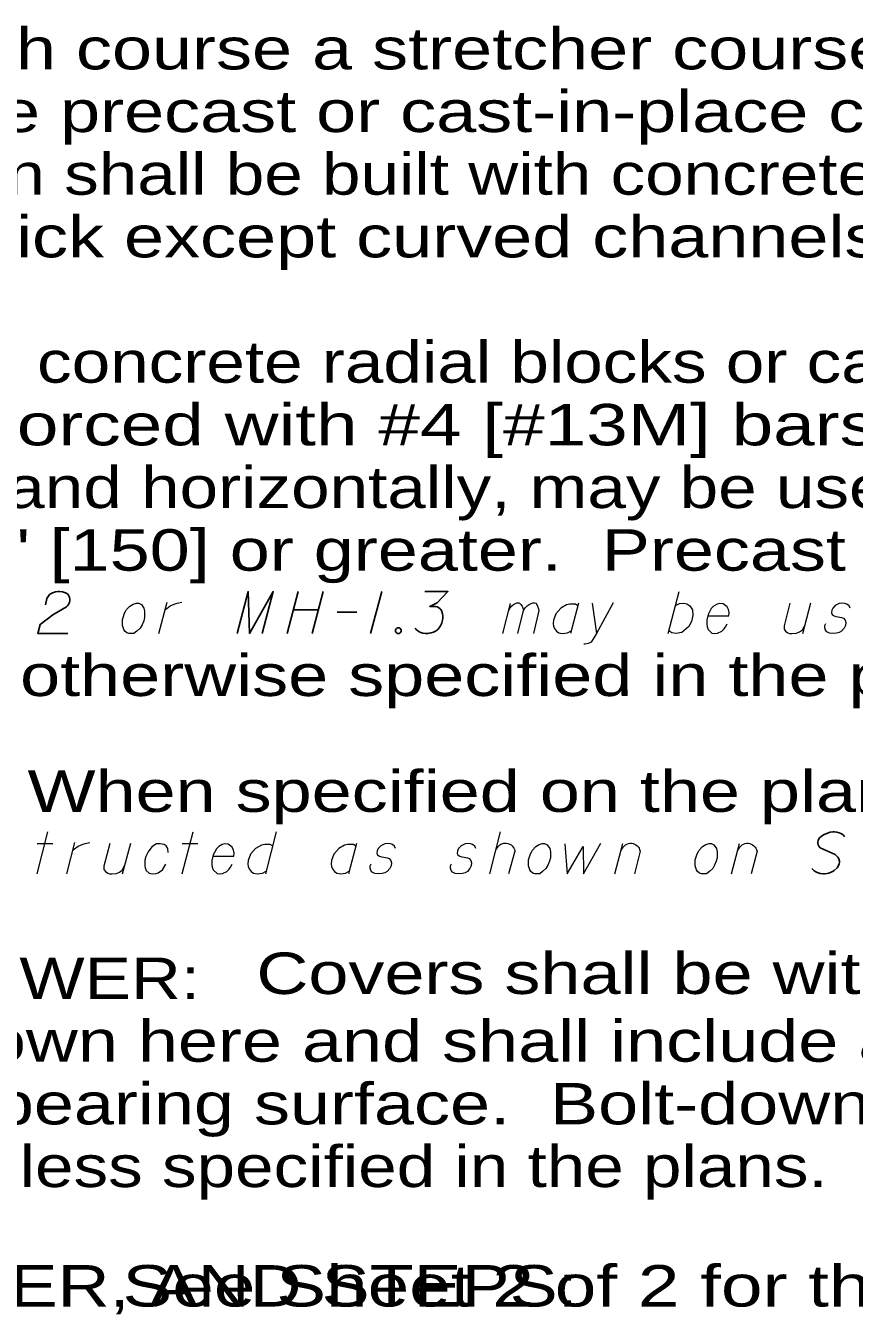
# Model space of a CAD drawing. Extents: x 1083.1 to 1117.1, y 697.4 to 741.4.
# Drawn here: x 1106.726 to 1109.847, y 730.897 to 735.749 of the extents above; entities that cross this region are included whole.
import ezdxf

# ---------------------------------------------------------------- set-up
doc = ezdxf.new("R2010")
doc.units = 0
doc.header["$LTSCALE"] = 0.062
doc.layers.add('1', color=7, linetype='Continuous', lineweight=13)

msp = doc.modelspace()

# ---------------------------------------------------------------- linework, layer by layer
at = {"layer": '1', "lineweight": 25}
for p, q in [((1107.7525, 733.61842), (1107.71033, 733.46108)), ((1107.84667, 733.61842), (1107.8045, 733.46108)), ((1108.06717, 733.61842), (1108.025, 733.46108)), ((1107.73392, 733.54908), (1107.82808, 733.54908)), ((1107.89867, 733.54042), (1107.973, 733.54042))]:
    msp.add_line(p, q, dxfattribs=at)
at = {"layer": '1'}
for p, q in [((1109.14617, 733.46108), (1109.18708, 733.61842)), ((1107.22725, 733.46108), (1107.25817, 733.57883)), ((1108.52308, 733.46108), (1108.55158, 733.57383)), ((1108.58, 733.46108), (1108.60108, 733.54658)), ((1108.808, 733.57508), (1108.77825, 733.46108)), ((1108.86, 733.57508), (1108.87608, 733.46108)), ((1109.65292, 733.46108), (1109.68383, 733.57633)), ((1106.769, 732.55567), (1106.80983, 732.713)), ((1107.31533, 732.55567), (1107.35617, 732.713)), ((1107.66958, 732.713), (1107.62875, 732.55567)), ((1108.47358, 732.55567), (1108.5145, 732.713)), ((1106.769, 732.66967), (1106.82842, 732.66967)), ((1106.8805, 732.55567), (1106.91142, 732.67342)), ((1107.09108, 732.55567), (1107.122, 732.67092)), ((1107.31533, 732.66967), (1107.37475, 732.66967)), ((1107.97192, 732.66967), (1107.94217, 732.55567)), ((1108.94442, 732.55567), (1108.97533, 732.66967)), ((1109.38417, 732.55567), (1109.41517, 732.66967))]:
    msp.add_line(p, q, dxfattribs=at)
at = {"layer": '1', "lineweight": 25}
for points in [[(1106.79983, 733.56892), (1106.806, 733.59242), (1106.81592, 733.60733), (1106.82708, 733.6135), (1106.83825, 733.61725), (1106.84692, 733.61842), (1106.85308, 733.61842), (1106.86425, 733.61725), (1106.87167, 733.61475), (1106.87542, 733.6135), (1106.88283, 733.60975), (1106.8865, 733.60483), (1106.889, 733.59983), (1106.89025, 733.59617), (1106.8915, 733.59117), (1106.8915, 733.585), (1106.89025, 733.57883), (1106.889, 733.57508), (1106.8865, 733.57017), (1106.88283, 733.56517), (1106.87908, 733.5615), (1106.82833, 733.5305), (1106.78, 733.49458), (1106.77133, 733.46108), (1106.88408, 733.46108)], [(1107.52208, 733.46108), (1107.56417, 733.61842), (1107.56917, 733.46108), (1107.65833, 733.61842), (1107.61617, 733.46108)], [(1108.22942, 733.61842), (1108.31617, 733.61842), (1108.27525, 733.57633), (1108.248, 733.56267), (1108.27033, 733.56267), (1108.27525, 733.5615), (1108.27775, 733.56025), (1108.28025, 733.559), (1108.28267, 733.55775), (1108.28767, 733.554), (1108.29017, 733.55033), (1108.29258, 733.54658), (1108.29383, 733.54292), (1108.29633, 733.53425), (1108.29758, 733.52675), (1108.29758, 733.52308), (1108.29758, 733.51808), (1108.29633, 733.51067), (1108.29508, 733.50575), (1108.29383, 733.50075), (1108.29258, 733.49708), (1108.29142, 733.49458), (1108.29017, 733.49208), (1108.28892, 733.48958), (1108.28642, 733.48592), (1108.28267, 733.48092), (1108.279, 733.47725), (1108.2765, 733.47475), (1108.27275, 733.47225), (1108.26908, 733.46983), (1108.26408, 733.46733), (1108.26167, 733.46608), (1108.253, 733.46358), (1108.2455, 733.46233), (1108.24058, 733.46108), (1108.23192, 733.46108), (1108.222, 733.46233), (1108.21825, 733.46358), (1108.21458, 733.46483), (1108.21083, 733.46608), (1108.20717, 733.46858), (1108.20342, 733.471), (1108.19725, 733.476), (1108.1935, 733.48092)], [(1109.81033, 732.6945), (1109.80783, 732.69942), (1109.80167, 732.70433), (1109.79667, 732.70683), (1109.7905, 732.70933), (1109.78183, 732.71183), (1109.77192, 732.713), (1109.76575, 732.713), (1109.75583, 732.71183), (1109.73967, 732.70558), (1109.731, 732.70192), (1109.72233, 732.69567), (1109.71617, 732.69075), (1109.71367, 732.687), (1109.71125, 732.68083), (1109.71, 732.67583), (1109.71, 732.67092), (1109.71125, 732.66475), (1109.71367, 732.65975), (1109.71742, 732.65483), (1109.71867, 732.65358), (1109.77442, 732.62758), (1109.78558, 732.61767), (1109.788, 732.61392), (1109.78925, 732.61142), (1109.79175, 732.60275), (1109.79175, 732.59783), (1109.7905, 732.59283), (1109.788, 732.58667), (1109.78308, 732.578), (1109.77067, 732.56808), (1109.767, 732.56558), (1109.75708, 732.56067), (1109.75083, 732.55817), (1109.74467, 732.55692), (1109.73475, 732.55567), (1109.731, 732.55567), (1109.71867, 732.55692), (1109.71125, 732.55942), (1109.705, 732.56192), (1109.69633, 732.56683), (1109.68767, 732.5755)]]:
    msp.add_lwpolyline(points, dxfattribs=at)
at = {"layer": '1'}
for points in [[(1107.143, 733.57508), (1107.15167, 733.57508), (1107.16158, 733.57017), (1107.17142, 733.5565), (1107.17267, 733.55033), (1107.17392, 733.54408), (1107.17392, 733.53917), (1107.17392, 733.52058), (1107.17025, 733.50817), (1107.164, 733.49333), (1107.15658, 733.48092), (1107.14417, 733.46983), (1107.13308, 733.46108), (1107.1145, 733.46108), (1107.107, 733.46358), (1107.09958, 733.46983), (1107.09592, 733.476), (1107.09092, 733.49083), (1107.09092, 733.51317), (1107.09342, 733.52058), (1107.09833, 733.53667), (1107.10333, 733.54533), (1107.10583, 733.55033), (1107.11817, 733.56392), (1107.13058, 733.57142)], [(1108.67183, 732.66967), (1108.6805, 732.66967), (1108.69042, 732.66475), (1108.70033, 732.65108), (1108.70158, 732.64492), (1108.70283, 732.63867), (1108.70283, 732.63375), (1108.70283, 732.61517), (1108.69908, 732.60275), (1108.69292, 732.58792), (1108.68542, 732.5755), (1108.67308, 732.56442), (1108.66192, 732.55567), (1108.64333, 732.55567), (1108.63592, 732.55817), (1108.6285, 732.56442), (1108.62475, 732.57058), (1108.61983, 732.58542), (1108.61983, 732.60775), (1108.62225, 732.61517), (1108.62725, 732.63125), (1108.63217, 732.63992), (1108.63467, 732.64492), (1108.64708, 732.6585), (1108.65942, 732.666)], [(1109.29992, 732.66967), (1109.30858, 732.66967), (1109.3185, 732.66475), (1109.32842, 732.65108), (1109.32967, 732.64492), (1109.33092, 732.63867), (1109.33092, 732.63375), (1109.33092, 732.61517), (1109.32717, 732.60275), (1109.321, 732.58792), (1109.31358, 732.5755), (1109.30117, 732.56442), (1109.29, 732.55567), (1109.27142, 732.55567), (1109.264, 732.55817), (1109.25658, 732.56442), (1109.25283, 732.57058), (1109.24792, 732.58542), (1109.24792, 732.60775), (1109.25033, 732.61517), (1109.25533, 732.63125), (1109.26025, 732.63992), (1109.26275, 732.64492), (1109.27517, 732.6585), (1109.2875, 732.666)]]:
    msp.add_lwpolyline(points, close=True, dxfattribs=at)
for points in [[(1107.25075, 733.55033), (1107.25692, 733.55525), (1107.27058, 733.56517), (1107.28542, 733.57142), (1107.29658, 733.57508), (1107.31392, 733.57883)], [(1108.54408, 733.54408), (1108.55033, 733.55775), (1108.5565, 733.56517), (1108.56392, 733.57017), (1108.57133, 733.57383), (1108.57633, 733.57633), (1108.58375, 733.57633), (1108.58625, 733.57508), (1108.59117, 733.57017), (1108.59617, 733.56392), (1108.59983, 733.55283), (1108.60108, 733.54658), (1108.60725, 733.55775), (1108.61475, 733.56517), (1108.62217, 733.57017), (1108.62958, 733.57383), (1108.63575, 733.57633), (1108.642, 733.57633), (1108.64692, 733.57508), (1108.65067, 733.57017), (1108.65433, 733.56392), (1108.65808, 733.55283), (1108.65933, 733.54658), (1108.63825, 733.46108)], [(1108.8055, 733.56517), (1108.79683, 733.57142), (1108.77575, 733.57142), (1108.76342, 733.56892), (1108.74108, 733.5565), (1108.7225, 733.53425), (1108.71383, 733.51067), (1108.71258, 733.49825), (1108.71383, 733.48842), (1108.71758, 733.47967), (1108.725, 733.46983), (1108.73367, 733.46358), (1108.74725, 733.46108), (1108.75717, 733.46233), (1108.76708, 733.46358), (1108.78075, 733.471)], [(1108.93933, 733.57633), (1108.87608, 733.46108), (1108.85633, 733.42767), (1108.85133, 733.42517), (1108.84517, 733.42275), (1108.83275, 733.42025), (1108.82783, 733.42025)], [(1109.17342, 733.56642), (1109.18833, 733.57383), (1109.20442, 733.57508), (1109.21683, 733.57258), (1109.22792, 733.56517), (1109.23783, 733.54908), (1109.23908, 733.528), (1109.23417, 733.50575), (1109.22425, 733.48717), (1109.197, 733.46483), (1109.17592, 733.46108), (1109.15983, 733.46358), (1109.14867, 733.471)], [(1109.29483, 733.52675), (1109.37408, 733.52675), (1109.37533, 733.53917), (1109.37292, 733.55033), (1109.36792, 733.5615), (1109.35308, 733.57258), (1109.34067, 733.57383), (1109.33075, 733.57142), (1109.31717, 733.56392), (1109.3085, 733.55525), (1109.301, 733.54167), (1109.29608, 733.53175), (1109.29108, 733.51067), (1109.29108, 733.49708), (1109.29233, 733.48592), (1109.29608, 733.476), (1109.31092, 733.46233), (1109.32083, 733.46108), (1109.33075, 733.46233), (1109.332, 733.46233), (1109.34808, 733.46983), (1109.35675, 733.4785), (1109.3605, 733.48467), (1109.36175, 733.48592), (1109.36792, 733.49708)], [(1109.60458, 733.57508), (1109.58225, 733.48958), (1109.58225, 733.47725), (1109.58842, 733.46983), (1109.59717, 733.46358), (1109.60333, 733.46108), (1109.612, 733.46108), (1109.62933, 733.46233), (1109.6405, 733.46733), (1109.65167, 733.47475), (1109.66158, 733.49333)], [(1109.83125, 733.5565), (1109.82758, 733.56517), (1109.81883, 733.57142), (1109.81142, 733.57383), (1109.80025, 733.57508), (1109.79042, 733.57383), (1109.7755, 733.56642), (1109.76558, 733.5565), (1109.76192, 733.54783), (1109.76067, 733.53792), (1109.76308, 733.53175), (1109.76808, 733.528), (1109.77058, 733.52675), (1109.778, 733.52433), (1109.78667, 733.52308), (1109.79908, 733.52058), (1109.8065, 733.51808), (1109.81267, 733.51067), (1109.81517, 733.502), (1109.81392, 733.49083), (1109.809, 733.48092), (1109.79908, 733.46983), (1109.79042, 733.46483), (1109.7805, 733.46233), (1109.76808, 733.46108), (1109.75325, 733.46233), (1109.74333, 733.46733), (1109.73833, 733.4735), (1109.73583, 733.48217), (1109.73583, 733.49083), (1109.73958, 733.49825)], [(1106.904, 732.64492), (1106.91017, 732.64983), (1106.92383, 732.65975), (1106.93867, 732.666), (1106.94983, 732.66967), (1106.96717, 732.67342)], [(1107.04275, 732.66967), (1107.02042, 732.58417), (1107.02042, 732.57183), (1107.02667, 732.56442), (1107.03533, 732.55817), (1107.0415, 732.55567), (1107.05017, 732.55567), (1107.0675, 732.55692), (1107.07867, 732.56192), (1107.08983, 732.56933), (1107.09975, 732.58792)], [(1107.262, 732.63625), (1107.26075, 732.65108), (1107.25458, 732.661), (1107.24717, 732.666), (1107.23225, 732.66842), (1107.21867, 732.66842), (1107.20133, 732.65733), (1107.18767, 732.63867), (1107.17775, 732.62017), (1107.17408, 732.6065), (1107.17408, 732.58542), (1107.17533, 732.578), (1107.18025, 732.56808), (1107.19142, 732.55817), (1107.20383, 732.55567), (1107.21742, 732.55692), (1107.22483, 732.55942), (1107.241, 732.57058), (1107.25333, 732.59167)], [(1107.4305, 732.62133), (1107.50975, 732.62133), (1107.511, 732.63375), (1107.50858, 732.64492), (1107.50358, 732.65608), (1107.48875, 732.66717), (1107.47633, 732.66842), (1107.46642, 732.666), (1107.45283, 732.6585), (1107.44417, 732.64983), (1107.43667, 732.63625), (1107.43175, 732.62633), (1107.42675, 732.60525), (1107.42675, 732.59167), (1107.428, 732.5805), (1107.43175, 732.57058), (1107.44658, 732.55692), (1107.4565, 732.55567), (1107.46642, 732.55692), (1107.46767, 732.55692), (1107.48375, 732.56442), (1107.49242, 732.57308), (1107.49617, 732.57925), (1107.49742, 732.5805), (1107.50358, 732.59167)], [(1107.656, 732.661), (1107.64733, 732.666), (1107.62625, 732.666), (1107.61383, 732.6635), (1107.59158, 732.65108), (1107.573, 732.62883), (1107.56433, 732.60525), (1107.56308, 732.59283), (1107.56433, 732.583), (1107.568, 732.57425), (1107.57542, 732.56442), (1107.58417, 732.55817), (1107.59775, 732.55567), (1107.60767, 732.55692), (1107.61758, 732.55817), (1107.63117, 732.56558)], [(1107.96942, 732.65975), (1107.96075, 732.666), (1107.93967, 732.666), (1107.92725, 732.6635), (1107.905, 732.65108), (1107.88642, 732.62883), (1107.87775, 732.60525), (1107.8765, 732.59283), (1107.87775, 732.583), (1107.88142, 732.57425), (1107.88892, 732.56442), (1107.89758, 732.55817), (1107.91117, 732.55567), (1107.92108, 732.55692), (1107.931, 732.55817), (1107.94467, 732.56558)], [(1108.11933, 732.65108), (1108.11558, 732.65975), (1108.10692, 732.666), (1108.0995, 732.66842), (1108.08833, 732.66967), (1108.07842, 732.66842), (1108.06358, 732.661), (1108.05367, 732.65108), (1108.04992, 732.64242), (1108.04867, 732.6325), (1108.05117, 732.62633), (1108.05608, 732.62258), (1108.05858, 732.62133), (1108.066, 732.61892), (1108.07467, 732.61767), (1108.08708, 732.61517), (1108.0945, 732.61267), (1108.10075, 732.60525), (1108.10317, 732.59658), (1108.10192, 732.58542), (1108.097, 732.5755), (1108.08708, 732.56442), (1108.07842, 732.55942), (1108.0685, 732.55692), (1108.05608, 732.55567), (1108.04125, 732.55692), (1108.03133, 732.56192), (1108.02642, 732.56808), (1108.02392, 732.57675), (1108.02392, 732.58542), (1108.02767, 732.59283)], [(1108.42158, 732.65108), (1108.41783, 732.65975), (1108.40917, 732.666), (1108.40175, 732.66842), (1108.39058, 732.66967), (1108.38067, 732.66842), (1108.36583, 732.661), (1108.35592, 732.65108), (1108.35225, 732.64242), (1108.351, 732.6325), (1108.35342, 732.62633), (1108.35842, 732.62258), (1108.36092, 732.62133), (1108.36833, 732.61892), (1108.377, 732.61767), (1108.38942, 732.61517), (1108.39683, 732.61267), (1108.403, 732.60525), (1108.4055, 732.59658), (1108.40425, 732.58542), (1108.39925, 732.5755), (1108.38942, 732.56442), (1108.38067, 732.55942), (1108.37083, 732.55692), (1108.35842, 732.55567), (1108.3435, 732.55692), (1108.33367, 732.56192), (1108.32867, 732.56808), (1108.32617, 732.57675), (1108.32617, 732.58542), (1108.32992, 732.59283)], [(1108.49717, 732.64617), (1108.50083, 732.65108), (1108.50583, 732.6585), (1108.50958, 732.66225), (1108.512, 732.66475), (1108.51575, 732.66717), (1108.51942, 732.66842), (1108.52317, 732.66967), (1108.52692, 732.67092), (1108.53558, 732.67092), (1108.54175, 732.66967), (1108.54917, 732.66717), (1108.55417, 732.66475), (1108.55783, 732.661), (1108.56158, 732.65608), (1108.56408, 732.65233), (1108.56533, 732.64983), (1108.56775, 732.64492), (1108.56775, 732.64117), (1108.54425, 732.55567)], [(1108.75608, 732.66842), (1108.766, 732.55567), (1108.82542, 732.6585), (1108.82667, 732.55567), (1108.89233, 732.67092)], [(1108.96792, 732.64242), (1108.97167, 732.64858), (1108.97658, 732.65608), (1108.98033, 732.65975), (1108.98525, 732.66475), (1108.99025, 732.66717), (1108.99642, 732.66967), (1109.00258, 732.67092), (1109.00758, 732.67092), (1109.01375, 732.66967), (1109.01875, 732.66717), (1109.02367, 732.66475), (1109.02858, 732.661), (1109.03358, 732.65608), (1109.03608, 732.65233), (1109.0385, 732.64742), (1109.041, 732.64117), (1109.01875, 732.55567)], [(1109.40767, 732.64242), (1109.41142, 732.64858), (1109.41633, 732.65608), (1109.42008, 732.65975), (1109.425, 732.66475), (1109.43, 732.66717), (1109.43617, 732.66967), (1109.44242, 732.67092), (1109.44733, 732.67092), (1109.4535, 732.66967), (1109.4585, 732.66717), (1109.46342, 732.66475), (1109.46842, 732.661), (1109.47333, 732.65608), (1109.47583, 732.65233), (1109.47833, 732.64742), (1109.48083, 732.64117), (1109.4585, 732.55567)]]:
    msp.add_lwpolyline(points, dxfattribs=at)
at = {"layer": '1', "lineweight": 25}
msp.add_lwpolyline([(1108.12658, 733.48217), (1108.13283, 733.48217), (1108.1365, 733.47967), (1108.14025, 733.47475), (1108.14025, 733.46858), (1108.1365, 733.46358), (1108.13283, 733.46108), (1108.12658, 733.46108), (1108.12292, 733.46358), (1108.11917, 733.46858), (1108.11917, 733.47475), (1108.12292, 733.47967)], close=True, dxfattribs=at)

# ---------------------------------------------------------------- texts
at = {"layer": '1'}
for s, width, p in [('with every sixth course a stretcher course.  The 6" [150]', 1.3, (1104.98617, 735.58508)), ('bottom may be precast or cast-in-place concrete.  The bottom', 1.3, (1104.98617, 735.34908)), ('channel section shall be built with concrete and lined with', 1.25, (1104.98617, 735.11308)), ('split pipe or brick except curved channels may be formed', 1.3, (1104.98617, 734.87708)), ('   Precast solid concrete radial blocks or cast-in-place', 1.25, (1104.98617, 734.40508)), ('concrete reinforced with #4 [#13M] bars on 12" [300] centers', 1.35, (1104.98617, 734.16908)), ('both vertically and horizontally, may be used with a wall', 1.25, (1104.98617, 733.93308)), ('thickness of 6" [150] or greater.  Precast manholes detailed', 1.3, (1104.98617, 733.69708)), ('shown unless otherwise specified in the plans.', 1.3, (1104.98617, 733.22508)), ('When specified on the plans, the drop pipe ', 1.3, (1106.73292, 732.78867)), ('SANITARY SEWER:', 1.25, (1104.97758, 732.08367)), ('Covers shall be without the pick and', 1.3, (1107.59483, 732.10283)), ('vent holes shown here and shall include a sealing gasket', 1.3, (1104.97758, 731.84767)), ('affixed to the bearing surface.  Bolt-down covers shall', 1.3, (1104.97758, 731.61167)), ('not be used unless specified in the plans.', 1.25, (1104.97758, 731.37567)), ('FRAME, COVER, AND STEPS:', 1.3, (1104.97758, 730.92567)), ('                           See Sheet 2 of 2 for these notes.', 1.35, (1104.97758, 730.92567))]:
    msp.add_text(s, height=0.156, dxfattribs=dict(at, width=width)).set_placement(p)

doc.saveas('drawing.dxf')
